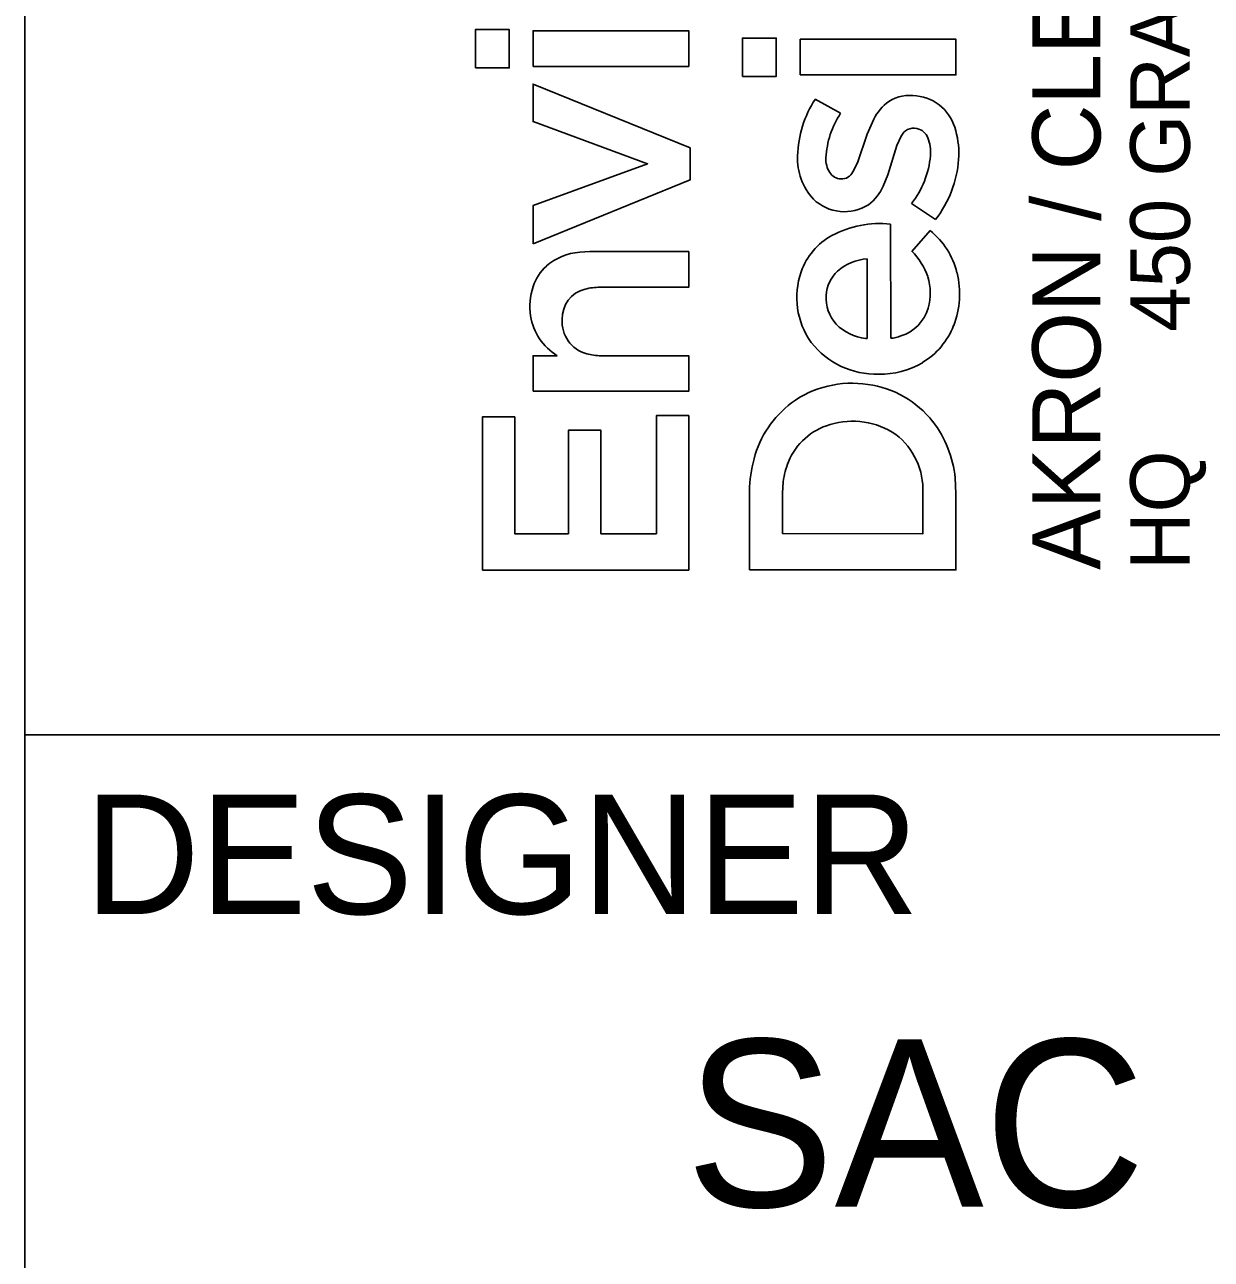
# Model space of a CAD drawing. Extents: x -0.4 to 34, y 0 to 22.
# Drawn here: x 32 to 32.993, y 2.061 to 3.094 of the extents above; entities that cross this region are included whole.
import ezdxf

# ---------------------------------------------------------------- set-up
doc = ezdxf.new("R2010")
doc.units = 0
doc.layers.add('SC_Scratch1', color=7, linetype='Continuous')
doc.layers.add('SH_Named_Boundary', color=7, linetype='Continuous')

msp = doc.modelspace()

# ---------------------------------------------------------------- linework, layer by layer
at = {"layer": 'SC_Scratch1'}
for p, q in [((32, 0.5), (32, 21.5)), ((32, 2.5), (33.5, 2.5))]:
    msp.add_line(p, q, dxfattribs=at)
at = {"layer": 'SH_Named_Boundary'}
for p, q in [((32.3771, 3.0582), (32.3771, 3.0903)), ((32.3771, 3.0903), (32.4054, 3.0903)), ((32.4054, 3.0903), (32.4054, 3.0582)), ((32.4254, 3.0594), (32.4254, 3.0893)), ((32.4254, 3.0893), (32.5557, 3.0893)), ((32.5557, 3.0893), (32.5557, 3.0594)), ((32.6005, 3.0511), (32.6005, 3.0832)), ((32.6005, 3.0832), (32.6289, 3.0832)), ((32.6289, 3.0832), (32.6289, 3.0511)), ((32.6489, 3.0523), (32.6489, 3.0822)), ((32.6489, 3.0822), (32.7792, 3.0822)), ((32.7792, 3.0822), (32.7792, 3.0523)), ((32.5557, 3.0594), (32.4254, 3.0594)), ((32.4054, 3.0582), (32.3771, 3.0582)), ((32.6289, 3.0511), (32.6005, 3.0511)), ((32.7792, 3.0523), (32.6489, 3.0523)), ((32.4254, 3.0133), (32.4254, 3.0446)), ((32.4254, 3.0446), (32.5567, 2.9913)), ((32.6615, 3.0321), (32.6827, 3.0203)), ((32.5212, 2.978), (32.4254, 3.0133)), ((32.7048, 3.0026), (32.7104, 3.0153)), ((32.6967, 2.9787), (32.7048, 3.0026)), ((32.7334, 3.001), (32.7298, 2.9933)), ((32.5567, 2.9913), (32.5567, 2.9644)), ((32.7298, 2.9933), (32.7221, 2.9688)), ((32.4254, 2.9429), (32.5212, 2.978)), ((32.693, 2.9712), (32.6967, 2.9787)), ((32.7221, 2.9688), (32.7182, 2.9592)), ((32.5567, 2.9644), (32.4254, 2.9109)), ((32.4254, 2.9109), (32.4254, 2.9429)), ((32.7621, 2.9314), (32.742, 2.9447)), ((32.7245, 2.9275), (32.7246, 2.8319)), ((32.7423, 2.9046), (32.7577, 2.922)), ((32.4644, 2.904), (32.4729, 2.9044)), ((32.4729, 2.9044), (32.5557, 2.9044)), ((32.5557, 2.9044), (32.5557, 2.8746)), ((32.7049, 2.8318), (32.7049, 2.8983)), ((32.5557, 2.8746), (32.4814, 2.8746)), ((32.7036, 2.8317), (32.7049, 2.8318)), ((32.4254, 2.7875), (32.4254, 2.8173)), ((32.4254, 2.8173), (32.4455, 2.8173)), ((32.4822, 2.8173), (32.5557, 2.8173)), ((32.5557, 2.8173), (32.5557, 2.7876)), ((32.5557, 2.7876), (32.4254, 2.7875)), ((32.383, 2.6379), (32.383, 2.766)), ((32.383, 2.766), (32.4101, 2.766)), ((32.4101, 2.766), (32.4101, 2.6683)), ((32.5286, 2.6683), (32.5286, 2.7672)), ((32.5286, 2.7672), (32.5557, 2.7672)), ((32.5557, 2.7672), (32.5557, 2.6379)), ((32.455, 2.6683), (32.455, 2.7549)), ((32.455, 2.7549), (32.4822, 2.7549)), ((32.4822, 2.7549), (32.4822, 2.6683)), ((32.6347, 2.7118), (32.6341, 2.7023)), ((32.7785, 2.715), (32.7792, 2.7021)), ((32.6064, 2.638), (32.6064, 2.704)), ((32.6341, 2.7023), (32.6341, 2.6684)), ((32.7515, 2.6683), (32.7515, 2.7024)), ((32.7792, 2.7021), (32.7792, 2.638)), ((32.4101, 2.6683), (32.455, 2.6683)), ((32.4822, 2.6683), (32.5286, 2.6683)), ((32.6341, 2.6684), (32.7515, 2.6683)), ((32.5557, 2.6379), (32.383, 2.6379)), ((32.7792, 2.638), (32.6064, 2.638))]:
    msp.add_line(p, q, dxfattribs=at)
for points in [[(32.3771, 3.0582), (32.3771, 3.0903), (32.4054, 3.0903), (32.4054, 3.0582)], [(32.4254, 3.0594), (32.4254, 3.0893), (32.5557, 3.0893), (32.5557, 3.0594)], [(32.6005, 3.0511), (32.6005, 3.0832), (32.6289, 3.0832), (32.6289, 3.0511)], [(32.6489, 3.0523), (32.6489, 3.0822), (32.7792, 3.0822), (32.7792, 3.0523)], [(32.4254, 2.9109), (32.4254, 2.9429), (32.5212, 2.978), (32.4254, 3.0133), (32.4254, 3.0446), (32.5567, 2.9913), (32.5567, 2.9644)], [(32.383, 2.6379), (32.383, 2.766), (32.4101, 2.766), (32.4101, 2.6683), (32.455, 2.6683), (32.455, 2.7549), (32.4822, 2.7549), (32.4822, 2.6683), (32.5286, 2.6683), (32.5286, 2.7672), (32.5557, 2.7672), (32.5557, 2.6379)]]:
    msp.add_lwpolyline(points, close=True, dxfattribs=at)
for points in [[(32.6615, 3.0321), (32.6827, 3.0203)], [(32.693, 2.9712), (32.6967, 2.9787), (32.7048, 3.0026), (32.7104, 3.0153)], [(32.7334, 3.001), (32.7298, 2.9933), (32.7221, 2.9688), (32.7182, 2.9592)], [(32.7621, 2.9314), (32.742, 2.9447)], [(32.7245, 2.9275), (32.7246, 2.8319)], [(32.7423, 2.9046), (32.7577, 2.922)], [(32.4644, 2.904), (32.4729, 2.9044), (32.5557, 2.9044), (32.5557, 2.8746), (32.4814, 2.8746)], [(32.7036, 2.8317), (32.7049, 2.8318), (32.7049, 2.8983)], [(32.4254, 2.7875), (32.4254, 2.8173), (32.4455, 2.8173)], [(32.4822, 2.8173), (32.5557, 2.8173), (32.5557, 2.7876), (32.4254, 2.7875)], [(32.7785, 2.715), (32.7792, 2.7021), (32.7792, 2.638), (32.6064, 2.638)], [(32.6347, 2.7118), (32.6341, 2.7023), (32.6341, 2.6684), (32.7515, 2.6683), (32.7515, 2.7024)], [(32.6064, 2.638), (32.6064, 2.704)]]:
    msp.add_lwpolyline(points, dxfattribs=at)
for centre, radius, start, end in [((32.7364, 2.9826), 0.0897, 146.531, 178.7571), ((32.7364, 2.9826), 0.0897, 146.531, 178.7571), ((32.7466, 2.9971), 0.0405, 125.5118, 153.4159), ((32.7466, 2.9971), 0.0405, 125.5118, 153.4159), ((32.7406, 3.0026), 0.0326, 80.1719, 122.5197), ((32.7406, 3.0026), 0.0326, 80.1719, 122.5197), ((32.7428, 2.9982), 0.0367, 47.7934, 84.6892), ((32.7428, 2.9982), 0.0367, 47.7934, 84.6892), ((32.7452, 2.9789), 0.0749, 146.5112, 176.9101), ((32.7452, 2.9789), 0.0749, 146.5112, 176.9101), ((32.7379, 2.9946), 0.0427, 14.9966, 46.2063), ((32.7379, 2.9946), 0.0427, 14.9966, 46.2063), ((32.7438, 2.9963), 0.0114, 76.6609, 155.7053), ((32.7438, 2.9963), 0.0114, 76.6609, 155.7053), ((32.744, 2.9951), 0.0126, 21.5098, 78.5262), ((32.744, 2.9951), 0.0126, 21.5098, 78.5262), ((32.7259, 2.9877), 0.0321, 354.5726, 22.068), ((32.7259, 2.9877), 0.0321, 354.5726, 22.068), ((32.7104, 2.9867), 0.0712, 355.8306, 15.3914), ((32.7104, 2.9867), 0.0712, 355.8306, 15.3914), ((32.6967, 2.9824), 0.0501, 177.5366, 222.7932), ((32.6967, 2.9824), 0.0501, 177.5366, 222.7932), ((32.6931, 2.9823), 0.0228, 178.4747, 211.0868), ((32.6931, 2.9823), 0.0228, 178.4747, 211.0868), ((32.6825, 2.9915), 0.0757, 321.811, 354.7969), ((32.6825, 2.9915), 0.0757, 321.811, 354.7969), ((32.6895, 2.9882), 0.0922, 321.9777, 355.8738), ((32.6895, 2.9882), 0.0922, 321.9777, 355.8738), ((32.6833, 2.9767), 0.0115, 212.2368, 268.3777), ((32.6833, 2.9767), 0.0115, 212.2368, 268.3777), ((32.6834, 2.9759), 0.0107, 267.716, 333.7337), ((32.6834, 2.9759), 0.0107, 267.716, 333.7337), ((32.681, 2.9758), 0.0408, 308.0877, 335.9874), ((32.681, 2.9758), 0.0408, 308.0877, 335.9874), ((32.686, 2.9753), 0.0375, 225.9854, 302.4797), ((32.686, 2.9753), 0.0375, 225.9854, 302.4797), ((32.7152, 2.8441), 0.0838, 83.615, 118.2876), ((32.7152, 2.8441), 0.0838, 83.615, 118.2876), ((32.7024, 2.8691), 0.0558, 118.8308, 160.6244), ((32.7024, 2.8691), 0.0558, 118.8308, 160.6244), ((32.7174, 2.8717), 0.0644, 13.5336, 51.3615), ((32.7174, 2.8717), 0.0644, 13.5336, 51.3615), ((32.4687, 2.8543), 0.0499, 94.9696, 130.2225), ((32.4687, 2.8543), 0.0499, 94.9696, 130.2225), ((32.7038, 2.8656), 0.0549, 19.0357, 45.4406), ((32.7038, 2.8656), 0.0549, 19.0357, 45.4406), ((32.7079, 2.8561), 0.0424, 94.008, 130.8817), ((32.7079, 2.8561), 0.0424, 94.008, 130.8817), ((32.4635, 2.8626), 0.0402, 132.2219, 161.6818), ((32.4635, 2.8626), 0.0402, 132.2219, 161.6818), ((32.7104, 2.8661), 0.0644, 160.5201, 215.7831), ((32.7104, 2.8661), 0.0644, 160.5201, 215.7831), ((32.7005, 2.8663), 0.0298, 132.9851, 177.179), ((32.7005, 2.8663), 0.0298, 132.9851, 177.179), ((32.7107, 2.8697), 0.047, 344.6059, 17.007), ((32.7107, 2.8697), 0.047, 344.6059, 17.007), ((32.7064, 2.8692), 0.0758, 339.3542, 13.3785), ((32.7064, 2.8692), 0.0758, 339.3542, 13.3785), ((32.4787, 2.8582), 0.056, 162.2736, 187.7919), ((32.4787, 2.8582), 0.056, 162.2736, 187.7919), ((32.4748, 2.8487), 0.025, 103.6865, 182.2187), ((32.4748, 2.8487), 0.025, 103.6865, 182.2187), ((32.4811, 2.8286), 0.046, 89.6049, 105.3284), ((32.4811, 2.8286), 0.046, 89.6049, 105.3284), ((32.7017, 2.865), 0.0311, 175.0013, 223.283), ((32.7017, 2.865), 0.0311, 175.0013, 223.283), ((32.7224, 2.8671), 0.035, 288.0077, 343.5508), ((32.7224, 2.8671), 0.035, 288.0077, 343.5508), ((32.4703, 2.858), 0.0476, 188.962, 238.7037), ((32.4703, 2.858), 0.0476, 188.962, 238.7037), ((32.4773, 2.8456), 0.0276, 175.5854, 255.1439), ((32.4773, 2.8456), 0.0276, 175.5854, 255.1439), ((32.7089, 2.8736), 0.0423, 225.0619, 262.7974), ((32.7089, 2.8736), 0.0423, 225.0619, 262.7974), ((32.7189, 2.8652), 0.0626, 300.9427, 338.7323), ((32.7189, 2.8652), 0.0626, 300.9427, 338.7323), ((32.7247, 2.8522), 0.0202, 269.7003, 294.8711), ((32.7247, 2.8522), 0.0202, 269.7003, 294.8711), ((32.7125, 2.8705), 0.0687, 217.7452, 271.6543), ((32.7125, 2.8705), 0.0687, 217.7452, 271.6543), ((32.4818, 2.8595), 0.0422, 254.0916, 270.5284), ((32.4818, 2.8595), 0.0422, 254.0916, 270.5284), ((32.7155, 2.8724), 0.0706, 269.2048, 300.3341), ((32.7155, 2.8724), 0.0706, 269.2048, 300.3341), ((32.6923, 2.7079), 0.0864, 81.194, 125.9984), ((32.6923, 2.7079), 0.0864, 81.194, 125.9984), ((32.6946, 2.7113), 0.0827, 37.8521, 82.402), ((32.6946, 2.7113), 0.0827, 37.8521, 82.402), ((32.6939, 2.7089), 0.0865, 127.2362, 165.148), ((32.6939, 2.7089), 0.0865, 127.2362, 165.148), ((32.6889, 2.7078), 0.054, 106.1881, 157.3861), ((32.6889, 2.7078), 0.054, 106.1881, 157.3861), ((32.6928, 2.6986), 0.0639, 55.6727, 107.2093), ((32.6928, 2.6986), 0.0639, 55.6727, 107.2093), ((32.6859, 2.7057), 0.0931, 5.7333, 37.304), ((32.6859, 2.7057), 0.0931, 5.7333, 37.304), ((32.6929, 2.705), 0.0587, 357.4662, 52.2665), ((32.6929, 2.705), 0.0587, 357.4662, 52.2665), ((32.7143, 2.7028), 0.1078, 164.7861, 179.3704), ((32.7143, 2.7028), 0.1078, 164.7861, 179.3704), ((32.6983, 2.7039), 0.0641, 157.3571, 172.9275), ((32.6983, 2.7039), 0.0641, 157.3571, 172.9275)]:
    msp.add_arc(centre, radius, start, end, dxfattribs=at)

# ---------------------------------------------------------------- texts
for s, height, p in [('450 GRANT ST., AKRON, OH  44311', 0.049846, (32.9749, 2.8374)), ('AKRON / CLEVELAND / COLUMBUS', 0.056969, (32.9001, 2.638)), ('HQ ', 0.04985, (32.9749, 2.638))]:
    msp.add_text(s, height=height, rotation=90, dxfattribs=at).set_placement(p)
for s, height, p in [('DESIGNER', 0.1, (32.05, 2.35)), ('SAC', 0.14, (32.5528, 2.105))]:
    msp.add_text(s, height=height, dxfattribs=at).set_placement(p)

doc.saveas('drawing.dxf')
